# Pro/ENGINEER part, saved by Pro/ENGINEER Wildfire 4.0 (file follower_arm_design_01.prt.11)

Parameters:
  METRIC = "NO"

Other parameters: PITCH, DRILL_DIAMETER, THREAD_DIAMETER, THREADS_PER_INCH, THREAD_DEPTH, THREAD_LENGTH, DRILL_POINT_ANGLE, DRILL_DEPTH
